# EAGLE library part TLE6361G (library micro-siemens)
Multi Voltage Microprocessor Power Supply
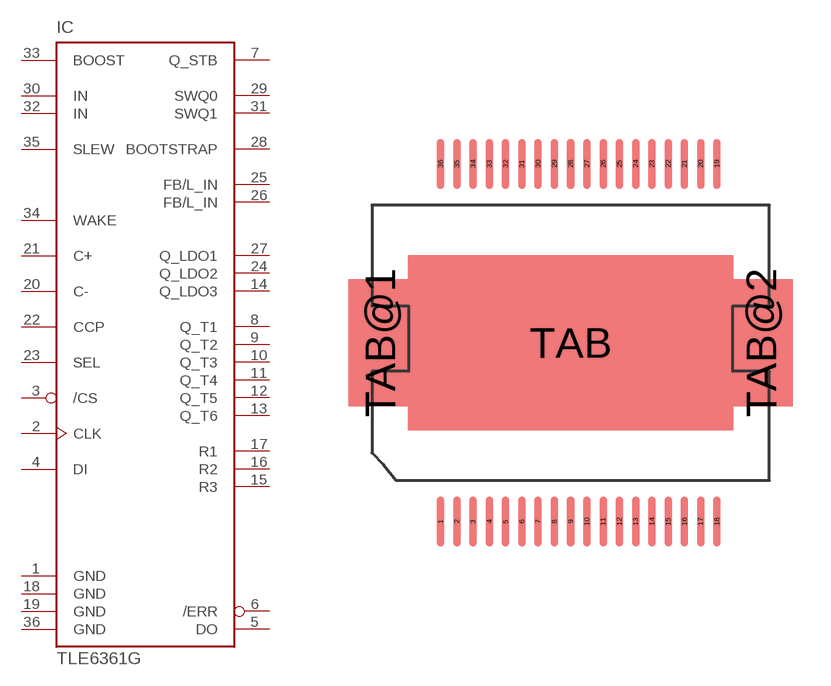
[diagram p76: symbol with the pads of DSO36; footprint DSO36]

Designator prefix IC

## TLE6361G (OC_FARNELL: unknown; OC_NEWARK: unknown)  [DSO36]
1  GND  pwr
2  CLK
3  /CS
4  DI
5  DO
6  /ERR
7  Q_STB
8  Q_T1
9  Q_T2
10  Q_T3
11  Q_T4
12  Q_T5
13  Q_T6
14  Q_LDO3
15  R3
16  R2
17  R1
18  GND  pwr
19  GND  pwr
20  C-
21  C+
22  CCP
23  SEL
24  Q_LDO2
25  FB/L_IN
26  FB/L_IN
27  Q_LDO1
28  BOOTSTRAP
29  SWQ0
30  IN
31  SWQ1
32  IN
33  BOOST
34  WAKE
35  SLEW
36  GND  pwr

## Footprint DSO36 (pad centres in mm)
DSO36 Source: TLE6361G
smd 0.3 x 2: 1 -5.2,-7.15; 2 -4.55,-7.15; 3 -3.9,-7.15; 4 -3.25,-7.15; 5 -2.6,-7.15; 6 -1.95,-7.15; 7 -1.3,-7.15; 8 -0.65,-7.15; 9 0,-7.15; 10 0.65,-7.15; 11 1.3,-7.15; 12 1.95,-7.15; 13 2.6,-7.15; 14 3.25,-7.15; 15 3.9,-7.15; 16 4.55,-7.15; 17 5.2,-7.15; 18 5.85,-7.15; 19 5.85,7.15; 20 5.2,7.15; 21 4.55,7.15; 22 3.9,7.15; 23 3.25,7.15; 24 2.6,7.15; 25 1.95,7.15; 26 1.3,7.15; 27 0.65,7.15; 28 0,7.15; 29 -0.65,7.15; 30 -1.3,7.15; 31 -1.95,7.15; 32 -2.6,7.15; 33 -3.25,7.15; 34 -3.9,7.15; 35 -4.55,7.15; 36 -5.2,7.15
smd 13 x 7: TAB 0,0
smd 2.543 x 5.08: TAB@1 -7.62,0; TAB@2 7.62,0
